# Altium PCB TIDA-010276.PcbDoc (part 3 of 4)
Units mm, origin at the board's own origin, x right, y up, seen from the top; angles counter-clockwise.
Board outline 146.48 x 90.27 mm, 4 copper layers (Top Layer, Signal Layer1, Signal Layer2, Bottom Layer), stack 1.631 mm thick; 271 components, 98 nets, 671 pads, 1828 vias.
Unrouted connection lines stored in the file: 2.
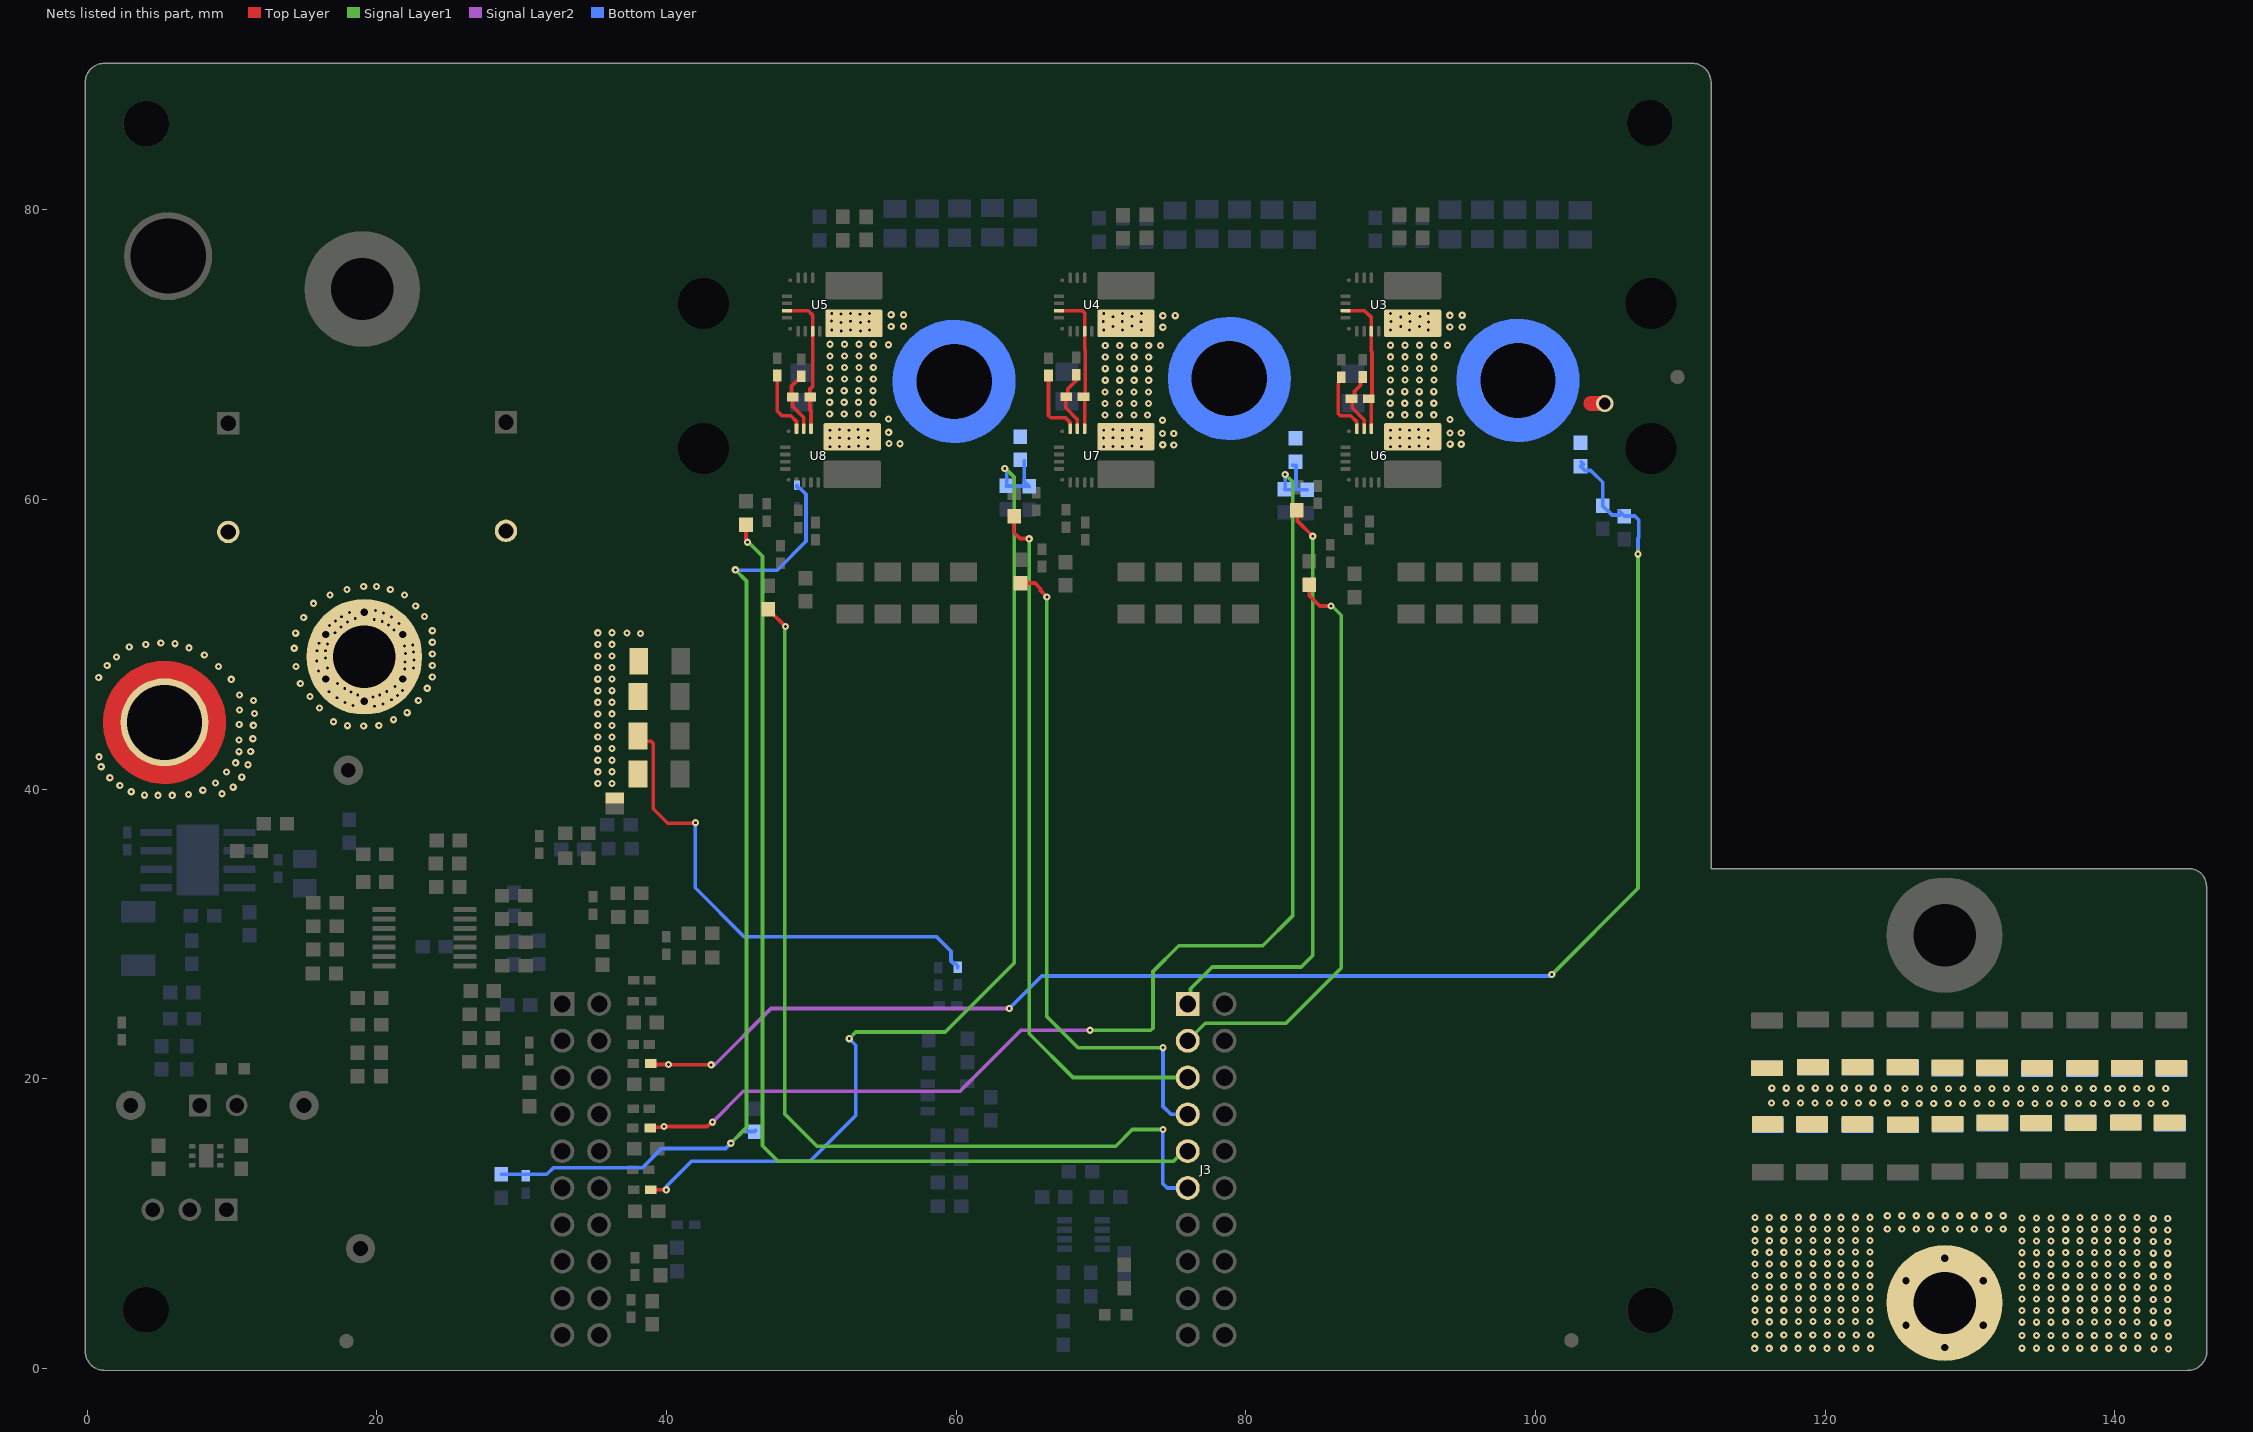
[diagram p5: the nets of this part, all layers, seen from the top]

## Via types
v1: diameter 0.5, hole 0.2, Top Layer to Bottom Layer, tented both sides, 1031 vias
v2: diameter 0.5, hole 0.2, Top Layer to Bottom Layer, 766 vias
v3: diameter 1, hole 0.5, Top Layer to Bottom Layer, 24 vias
v4: diameter 0.63, hole 0.33, Top Layer to Bottom Layer, tented both sides, 6 vias
v5: diameter 1.2, hole 0.8, Top Layer to Bottom Layer, 1 vias

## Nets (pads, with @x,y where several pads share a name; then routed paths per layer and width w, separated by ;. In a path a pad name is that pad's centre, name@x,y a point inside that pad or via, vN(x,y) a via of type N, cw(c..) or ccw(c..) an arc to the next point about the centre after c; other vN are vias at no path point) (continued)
PGND: C1.2 C2.2 C3.2 C4.2 C5.2 C6.2 C7.2 C8.2 C9.2 C10.2 C11.2 C12.2 C13.2 C14.2 C15.2 C16.2 C17.2 C18.2 C19.2 C20.2 C21.2 C22.2 C23.2 C24.2 C25.2 C26.2 C27.2 C28.2 C29.2 C30.2 C31.2 C32.2 C33.2 C34.2 C35.2 C36.2 C37.2 C38.2 C39.2 C40.1 C41.1 C42.1 MHA3.1 MHA4.1 MP3.1 NT1.1 R41.1 R42.1 R43.1 R44.1 R45.2 | length 34.7
  Top Layer w0.254: NT1.1@36.443,39.343 NT1.1@36.443,39.394 ; R41.1@37.844,48.83 R41.1@38.094,48.83 ; R43.1@37.965,43.307 38.945,43.307 39.093,43.158 39.093,38.645 40.094,37.644 41.971,37.644 v1(42.012,37.685)
  Bottom Layer w0.254: v1(42.012,37.685) 41.989,37.662 41.989,33.194 45.366,29.817 58.646,29.817 59.656,28.807 59.656,28.144 59.831,27.969 59.944,27.969 60.104,27.809 R45.2@60.104,27.696
  other v1: 142.708,1.355 143.708,1.355 115.137,1.398 116.137,1.398 117.137,1.398 118.137,1.398 119.137,1.398 120.137,1.398 121.137,1.398 122.137,1.398 123.137,1.398 133.59,1.408 134.59,1.408 135.59,1.408 136.59,1.408 137.59,1.408 138.59,1.408 139.59,1.408 140.59,1.408 141.59,1.408 142.708,2.237 143.708,2.237 133.59,2.29 134.59,2.29 135.59,2.29 136.59,2.29 137.59,2.29 138.59,2.29 139.59,2.29 140.59,2.29 141.59,2.29 115.152,2.311 116.152,2.311 117.152,2.311 118.152,2.311 119.152,2.311 120.152,2.311 121.152,2.311 122.152,2.311 123.152,2.311 142.659,3.169 143.659,3.169 133.59,3.205 134.59,3.205 135.59,3.205 115.152,3.225 116.152,3.225 117.152,3.225 136.608,3.222 137.608,3.222 138.608,3.222 139.541,3.222 140.541,3.222 141.541,3.222 118.17,3.243 119.17,3.243 120.17,3.243 121.103,3.243 122.103,3.243 123.103,3.243 142.659,3.969 143.659,3.969 133.59,4.005 134.59,4.005 135.59,4.005 115.152,4.025 116.152,4.025 117.152,4.025 118.17,4.043 119.17,4.043 120.17,4.043 121.103,4.043 122.103,4.043 123.103,4.043 136.608,4.022 137.608,4.022 138.608,4.022 139.541,4.022 140.541,4.022 141.541,4.022 142.659,4.769 143.659,4.769 133.59,4.805 134.59,4.805 135.59,4.805 115.152,4.825 116.152,4.825 117.152,4.825 136.608,4.822 137.608,4.822 138.608,4.822 139.541,4.822 140.541,4.822 141.541,4.822 118.17,4.843 119.17,4.843 120.17,4.843 121.103,4.843 122.103,4.843 123.103,4.843 142.659,5.569 143.659,5.569 133.59,5.605 134.59,5.605 135.59,5.605 115.152,5.625 116.152,5.625 117.152,5.625 118.17,5.643 119.17,5.643 120.17,5.643 121.103,5.643 122.103,5.643 123.103,5.643 136.608,5.622 137.608,5.622 138.608,5.622 139.541,5.622 140.541,5.622 141.541,5.622 142.659,6.369 143.659,6.369 133.59,6.405 134.59,6.405 135.59,6.405 115.152,6.425 116.152,6.425 117.152,6.425 136.608,6.422 137.608,6.422 138.608,6.422 139.541,6.422 140.541,6.422 141.541,6.422 118.17,6.443 119.17,6.443 120.17,6.443 121.103,6.443 122.103,6.443 123.103,6.443 142.659,7.169 143.659,7.169 133.59,7.205 134.59,7.205 135.59,7.205 115.152,7.225 116.152,7.225 117.152,7.225 118.17,7.243 119.17,7.243 120.17,7.243 121.103,7.243 122.103,7.243 123.103,7.243 136.608,7.222 137.608,7.222 138.608,7.222 139.541,7.222 140.541,7.222 141.541,7.222 142.659,7.969 143.659,7.969 133.59,8.005 134.59,8.005 135.59,8.005 115.152,8.025 116.152,8.025 117.152,8.025 136.608,8.022 137.608,8.022 138.608,8.022 139.541,8.022 140.541,8.022 141.541,8.022 118.17,8.043 119.17,8.043 120.17,8.043 121.103,8.043 122.103,8.043 123.103,8.043 142.659,8.769 143.659,8.769 133.59,8.805 134.59,8.805 135.59,8.805 115.152,8.825 116.152,8.825 117.152,8.825 118.17,8.843 119.17,8.843 120.17,8.843 121.103,8.843 122.103,8.843 123.103,8.843 136.608,8.822 137.608,8.822 138.608,8.822 139.541,8.822 140.541,8.822 141.541,8.822 142.659,9.569 143.659,9.569 133.59,9.605 134.59,9.605 135.59,9.605 115.152,9.625 116.152,9.625 117.152,9.625 136.608,9.622 137.608,9.622 138.608,9.622 139.541,9.622 140.541,9.622 141.541,9.622 118.17,9.643 119.17,9.643 120.17,9.643 121.103,9.643 122.103,9.643 123.103,9.643 124.297,9.643 125.297,9.643 126.297,9.643 127.297,9.643 128.297,9.643 129.297,9.643 130.297,9.643 131.297,9.643 132.297,9.643 142.659,10.369 143.659,10.369 133.59,10.405 134.59,10.405 135.59,10.405 115.152,10.425 116.152,10.425 117.152,10.425 118.17,10.443 119.17,10.443 120.17,10.443 121.103,10.443 122.103,10.443 123.103,10.443 136.608,10.422 137.608,10.422 138.608,10.422 139.541,10.422 140.541,10.422 141.541,10.422 124.297,10.554 125.297,10.554 126.297,10.554 127.297,10.554 128.297,10.554 129.297,10.554 130.297,10.554 131.297,10.554 132.297,10.554 125.495,18.307 126.495,18.307 127.495,18.307 128.495,18.307 129.495,18.307 130.495,18.307 131.495,18.307 132.495,18.307 133.495,18.307 134.495,18.307 135.495,18.307 136.495,18.307 137.495,18.307 138.495,18.307 139.495,18.307 140.495,18.307 141.495,18.307 142.495,18.307 143.495,18.307 116.298,18.329 117.298,18.329 118.298,18.329 119.298,18.329 120.298,18.329 121.298,18.329 122.298,18.329 123.298,18.329 124.298,18.329 116.325,19.359 117.325,19.359 118.325,19.359 119.325,19.359 120.325,19.359 121.325,19.359 122.325,19.359 123.325,19.359 124.325,19.359 125.522,19.337 126.522,19.337 127.522,19.337 128.522,19.337 129.522,19.337 130.522,19.337 131.522,19.337 132.522,19.337 133.522,19.337 134.522,19.337 135.521,19.337 136.521,19.337 137.521,19.337 138.521,19.337 139.521,19.337 140.521,19.337 141.521,19.337 142.521,19.337 143.521,19.337 4.898,39.577 5.886,39.577 3.969,39.592 7,39.632 9.315,39.684 3.052,39.826 7.996,39.931 10.091,40.142 2.264,40.26 8.873,40.421 1.575,40.792 10.685,40.831 9.633,41.181 0.978,41.548 11.119,41.692 10.263,41.822 0.819,42.234 10.485,42.591 11.299,42.598 10.499,43.404 11.447,43.487 19.098,44.36 17.989,44.386 20.145,44.398 11.482,44.412 10.507,44.464 17.018,44.661 21.167,44.802 11.561,45.227 22.104,45.287 10.533,45.467 16.051,45.603 19.838,45.73 18.362,45.778 20.437,45.895 17.82,45.997 11.497,46.122 22.875,46.129 21.034,46.175 17.259,46.314 19.756,46.379 15.392,46.403 21.422,46.463 10.533,46.496 18.69,46.507 20.212,46.51 18.225,46.704 16.708,46.73 20.691,46.746 21.772,46.814 17.794,46.964 23.487,46.971 21.253,47.09 14.727,47.303 17.299,47.312 9.961,47.589 0.803,47.708 23.841,47.745 15.986,48.165 21.933,48.299 16.594,48.368 22.53,48.357 9.083,48.469 14.426,48.465 1.389,48.538 23.841,48.545 21.959,48.783 15.861,48.84 22.578,48.934 16.478,49.053 2.043,49.128 8.099,49.269 21.991,49.357 23.841,49.345 22.539,49.463 15.89,49.564 16.478,49.564 14.31,49.73 7.038,49.76 2.918,49.813 21.92,49.889 22.488,49.957 4.051,49.998 16.612,50.026 6.066,50.048 5.094,50.093 16.015,50.075 23.841,50.145 14.403,50.775 17.111,50.803 23.841,50.945 21.19,50.995 17.525,51.188 16.746,51.303 20.814,51.342 21.544,51.436 17.996,51.544 20.381,51.572 17.15,51.601 19.833,51.717 18.516,51.794 14.958,51.858 21.016,51.88 17.563,51.909 23.301,51.926 20.468,52.169 18.121,52.198 19.91,52.342 22.692,52.645 15.632,52.836 16.778,53.407 21.911,53.407 17.955,53.788 20.942,53.788 19.098,54 19.99,54
  other v2: 35.266,40.398 36.238,40.403 35.266,41.198 36.238,41.203 35.266,41.998 36.238,42.003 35.266,42.798 36.238,42.803 35.266,43.598 36.238,43.603 35.266,44.398 36.238,44.403 35.266,45.198 36.238,45.203 35.266,45.998 36.238,46.003 35.266,46.798 36.238,46.803 35.266,47.598 36.238,47.603 35.266,48.398 36.238,48.403 35.266,49.198 36.238,49.203 35.266,49.998 36.238,50.003 38.215,50.757 35.266,50.798 36.238,50.803 37.278,50.791
  other v3: 128.254,1.46 125.591,2.998 130.917,2.998 125.591,6.072 130.917,6.072 128.254,7.61 19.143,46.069 16.48,47.607 21.806,47.607 16.48,50.681 21.806,50.681 19.143,52.219
Phase_U: MP2.1 R71.2 U3.6 U6.7 | length 1
  Top Layer w0.254: v5@104.796,66.628 v5(104.799,66.631)
  Top Layer w1.016: 103.83,66.628 v5@104.796,66.628
  other v1: 90,63.647 91.3,63.647 92.6,63.647 90,64.787 91.3,64.787 92.6,64.787 90,71.716 91.3,71.716 92.6,71.716 90,72.856 91.3,72.856 92.6,72.856
  other v2: 90.649,63.678 91.961,63.703 94.114,63.825 94.88,63.815 92.592,64.212 91.296,64.232 89.991,64.246 90.635,64.268 91.954,64.286 94.096,64.602 94.872,64.601 90.642,64.844 91.936,64.847 94.095,65.52 89.978,65.847 90.978,65.847 91.978,65.847 92.978,65.847 89.978,66.647 90.978,66.647 91.978,66.647 92.978,66.647 89.978,67.447 90.978,67.447 91.978,67.447 92.978,67.447 89.995,68.251 90.995,68.251 91.995,68.251 92.995,68.251 89.995,69.051 90.995,69.051 91.995,69.051 92.995,69.051 89.995,69.851 90.995,69.851 91.995,69.851 92.995,69.851 89.995,70.651 90.995,70.651 91.995,70.651 92.995,70.651 93.938,70.651 94.093,71.916 94.951,71.921 90.7,71.942 92.009,71.958 92.631,72.257 90.025,72.284 91.339,72.287 90.706,72.608 92.022,72.629 94.093,72.716 94.951,72.721
Phase_V: MP4.1 R72.2 U4.6 U7.7
  other v1: 70.2,63.647 71.5,63.647 72.8,63.647 70.2,64.787 71.5,64.787 72.8,64.787 70.2,71.716 71.5,71.716 72.8,71.716 70.2,72.856 71.5,72.856 72.8,72.856
  other v2: 70.846,63.674 72.158,63.7 74.272,63.783 75.038,63.773 72.789,64.208 70.188,64.242 71.493,64.229 70.833,64.264 72.151,64.282 74.254,64.56 75.029,64.559 70.839,64.84 72.134,64.844 74.253,65.478 70.281,65.83 71.281,65.83 72.281,65.83 73.216,65.836 70.281,66.63 71.281,66.63 72.281,66.63 73.281,66.63 70.281,67.43 71.281,67.43 72.281,67.43 73.281,67.43 70.299,68.234 71.299,68.234 72.299,68.234 73.299,68.234 70.299,69.034 71.299,69.034 72.299,69.034 73.299,69.034 70.299,69.834 71.299,69.834 72.299,69.834 73.299,69.834 70.299,70.634 71.299,70.634 72.299,70.634 73.299,70.634 74.122,70.627 74.277,71.892 70.838,71.958 72.148,71.974 72.769,72.273 70.164,72.3 71.477,72.302 70.844,72.624 72.161,72.644 74.277,72.692 75.135,72.697
Phase_W: MP5.1 R73.2 U5.6 U8.7
  other v1: 51.309,63.647 52.609,63.647 53.909,63.647 51.309,64.787 52.609,64.787 53.909,64.787 51.42,71.716 52.72,71.716 54.02,71.716 51.42,72.856 52.72,72.856 54.02,72.856
  other v2: 51.955,63.673 53.268,63.699 55.363,63.862 56.129,63.852 53.899,64.207 51.297,64.242 52.603,64.228 51.942,64.264 53.261,64.282 55.345,64.639 51.948,64.84 53.243,64.843 55.344,65.557 51.273,65.914 52.273,65.914 53.273,65.914 54.273,65.914 51.273,66.714 52.273,66.714 53.273,66.714 54.273,66.714 51.273,67.514 52.273,67.514 53.273,67.514 54.273,67.514 51.29,68.319 52.29,68.319 53.29,68.319 54.29,68.319 51.29,69.119 52.29,69.119 53.29,69.119 54.29,69.119 51.29,69.919 52.29,69.919 53.29,69.919 54.29,69.919 55.336,70.685 51.29,70.719 52.29,70.719 53.29,70.719 54.29,70.719 52.071,71.637 53.4,71.647 55.52,71.956 56.378,71.961 52.058,72.227 53.393,72.229 53.998,72.292 52.702,72.312 51.396,72.326 55.52,72.756 56.378,72.761 52.065,72.803 53.375,72.791
Temp: C123.1 R58.1 R87.2 RT1.2 | length 69.1
  Signal Layer1 w0.254: v1(44.45,15.559) 45.534,16.643 45.534,54.374 v1(44.763,55.145)
  Bottom Layer w0.254: C123.1@28.595,13.413 31.747,13.413 32.189,13.856 38.328,13.856 39.662,15.19 44.082,15.19 v1(44.45,15.559) 45.265,16.374 46.095,16.374 R58.1@46.159,16.438 ; v1(44.763,55.145) 44.791,55.117 47.648,55.117 49.644,57.112 49.644,60.365 49.227,60.782 49.092,60.782 49.019,60.855 RT1.2@49.019,60.99
U_H: J3.1 R16.2 | length 42.2
  Top Layer w0.254: J3.1@75.819,25.2 J3.1@76.19,25.572 ; R16.2@83.527,59.245 83.578,59.193 83.578,58.512 v1(84.625,57.465)
  Signal Layer1 w0.254: J3.1@75.997,25.171 76.19,25.365 76.19,26.229 77.69,27.728 83.838,27.728 84.625,28.515 v1(84.625,57.465)
U_HO: R10.1 U6.10 | length 4.6
  Top Layer w0.254: R10.1@86.593,68.444 86.42,68.271 86.42,68.054 86.388,68.022 86.388,65.941 86.537,65.792 87.245,65.792 87.675,65.362 U6.10@87.675,64.887
U_L: J3.3 R19.2 | length 40.4
  Top Layer w0.254: R19.2@84.384,54.129 84.384,53.379 85.118,52.645 v1(85.885,52.645)
  Signal Layer1 w0.254: J3.3@75.997,22.631 77.212,23.846 82.782,23.846 86.6,27.665 86.6,52.004 v1@86.01,52.594
U_SW: C81.2 U3.4 U3.14 U6.8 | length 9.9
  Top Layer w0.254: U3.14@86.9,73.041 88.205,73.041 88.675,72.571 U3.4@88.675,71.616 88.675,70.242 88.717,70.2 88.717,67.125 88.544,66.952 C81.2@88.501,66.952 88.675,66.779 U6.8@88.675,64.887
U_VCC: C81.1 R7.1 U6.9 | length 4
  Top Layer w0.254: R7.1@88.087,68.463 87.929,68.305 87.929,67.89 87.511,67.472 87.511,67.112 87.351,66.952 87.351,66.333 88.173,65.511 U6.9@88.173,65.11
U_Voltage: C117.1 R71.1 R75.2 R85.1 | length 105.8
  Top Layer w0.254: R85.1@38.915,21.061 38.987,20.989 v1(40.137,20.989) 40.146,20.98 43.082,20.98 v1(43.091,20.972)
  Signal Layer2 w0.254: v1(43.091,20.972) 43.336,20.972 47.227,24.863 v1(63.67,24.863)
  Signal Layer1 w0.254: v1@101.173,27.249 107.081,33.157 107.081,56.488
  Bottom Layer w0.254: v1(63.67,24.863) 65.914,27.107 v1@101.173,27.107 ; R71.1@103.121,62.312 103.424,62.009 103.824,62.009 104.643,61.19 104.643,59.554 104.991,59.206 105.016,59.206 105.287,58.935 R75.2@105.846,58.935 ; R71.1@103.165,62.6 R71.1@103.32,62.445 ; R75.2@105.781,59.233 106.129,58.885 R75.2@106.129,58.86 106.859,58.86 107.132,58.587 107.132,57.385 107.081,57.334 v1(107.081,56.231)
  other v1: 101.128,27.204
V_H: J3.5 R17.2 | length 48.8
  Top Layer w0.254: R17.2@64.014,58.862 63.985,58.833 63.985,57.746 64.416,57.315 65.02,57.315 v1(65.047,57.288)
  Signal Layer1 w0.254: v1(65.047,57.288) 65.047,23.117 68.073,20.091 J3.5@75.997,20.091
V_HO: R11.1 U7.10 | length 4.7
  Top Layer w0.254: R11.1@66.384,68.564 66.384,65.793 66.533,65.644 67.551,65.644 67.873,65.322 U7.10@67.873,65.11
V_L: J3.7 R20.2 | length 47
  Top Layer w0.254: R20.2@64.458,54.236 65.443,54.236 65.833,53.846 65.833,53.724 66.269,53.288 v1(66.269,53.268)
  Signal Layer1 w0.254: v1(66.269,53.268) 66.269,24.314 68.427,22.156 v1(74.289,22.156)
  Bottom Layer w0.254: v1(74.289,22.156) 74.289,18.1 74.837,17.551 J3.7@75.997,17.551 ; J3.7@76.043,17.912 76.357,17.912 J3.7@76.718,17.551
V_SW: C82.2 U4.4 U4.14 U7.8 | length 9.9
  Top Layer w0.254: U4.14@67.1,73.041 68.726,73.041 68.875,72.892 U4.4@68.875,71.616 68.875,70.4 68.931,70.344 68.931,67.278 68.914,67.262 68.875,67.262 U7.8@68.875,64.887
V_VCC: C82.1 R8.1 U7.9 | length 4.4
  Top Layer w0.254: R8.1@68.252,68.559 R8.1@68.3,68.607 ; R8.1@68.365,68.559 68.365,68.292 67.711,67.637 67.711,67.251 67.565,67.105 67.565,66.344 68.375,65.535 U7.9@68.375,64.887
V_Voltage: C118.1 R72.1 R76.2 R86.1 | length 87.8
  Top Layer w0.254: R86.1@38.884,16.608 38.942,16.666 39.78,16.666 v1(39.827,16.713) 42.811,16.713 43.112,17.014 v1(43.178,17.014)
  Signal Layer2 w0.254: v1(43.178,17.014) 45.314,19.149 60.276,19.149 64.482,23.355 v1(69.242,23.355)
  Signal Layer1 w0.254: v1(69.242,23.355) 73.45,23.355 73.598,23.504 73.598,27.415 75.368,29.185 81.167,29.185 83.236,31.253 83.236,61.223 v1(82.722,61.737)
  Bottom Layer w0.254: v1(82.722,61.737) 82.722,60.746 C118.1@82.684,60.707 82.722,60.669 83.464,60.669 ; R72.1@83.255,62.389 R72.1@83.284,62.36 ; R72.1@83.464,62.378 83.464,60.669 ; R76.2@84.252,60.669 83.464,60.669
W_H: J3.9 R18.2 | length 73.5
  Top Layer w0.254: R18.2@45.492,58.267 45.492,57.224 45.598,57.118 v1(45.598,57.051)
  Signal Layer1 w0.254: v1(45.598,57.051) 45.665,57.051 45.788,56.928 45.793,56.928 46.633,56.088 46.633,15.391 47.72,14.305 74.998,14.305 75.705,15.011 J3.9@75.997,15.011
W_HO: R12.1 U8.10 | length 4.6
  Top Layer w0.254: R12.1@47.657,68.564 47.658,66.115 47.988,65.784 48.588,65.784 48.984,65.388 U8.10@48.984,64.887
W_L: J3.11 R21.2 | length 68.4
  Top Layer w0.254: R21.2@46.991,52.364 47.079,52.364 v1(48.216,51.226)
  Signal Layer1 w0.254: v1(48.216,51.226) 48.178,51.188 48.178,17.582 50.401,15.358 71.017,15.358 72.165,16.506 v1(74.279,16.506)
  Bottom Layer w0.254: v1(74.279,16.506) 74.279,12.766 74.574,12.471 J3.11@75.997,12.471
W_SW: C83.2 U5.4 U5.14 U8.8 | length 9.9
  Top Layer w0.254: U5.14@48.32,73.041 49.787,73.041 50.095,72.733 50.095,67.809 49.922,67.636 49.912,67.636 49.912,66.186 49.984,66.115 U8.8@49.984,64.887
W_VCC: C83.1 R9.1 U8.9 | length 4.3
  Top Layer w0.254: 48.71,66.415 C83.1@48.71,67.074 ; C83.1@48.719,67.074 48.635,67.158 48.635,67.831 49.03,68.225 49.13,68.225 49.303,68.398 R9.1@49.303,68.498 ; 48.759,66.395 49.484,65.669 U8.9@49.484,64.887
W_Voltage: C119.1 R73.1 R77.2 R88.1 | length 74.6
  Top Layer w0.254: R88.1@38.934,12.355 38.949,12.339 v1(39.99,12.339)
  Signal Layer1 w0.254: v1(52.622,22.78) 53.079,23.236 59.254,23.236 64.009,27.992 64.009,61.556 63.428,62.137 v1(63.362,62.137)
  Bottom Layer w0.254: v1(39.99,12.339) 40.038,12.388 40.038,12.628 41.715,14.305 49.904,14.305 53.079,17.48 53.079,22.324 v1(52.622,22.78) ; v1(63.362,62.137) 63.362,62.07 63.493,61.939 63.493,60.959 C119.1@63.473,60.938 R77.2@65.025,60.938 ; R73.1@64.712,62.671 64.712,61.424 64.713,61.423 64.713,61.25 R77.2@65.025,60.938 ; R77.2@65.061,60.902 R77.2@65.025,60.938
pads on no net: FID1.1 FID2.1 FID3.1 J3.4 J3.6 J3.8 J3.10 J3.12 J3.14 J3.15 J3.16 J3.17 J3.18 J3.19 J4.5 J4.7 J4.9 J4.13 J4.15 J4.17 J4.19 J4.20 MP1. MP2. MP3. MP4. MP5. MP6. MP7. MP8. MP9. U1.5 U1.7@8.238,14.24 U1.7@8.238,15.14 U2.6 U3.1 U3.5 U3.8 U3.9 U3.10 U3.11 U3.12 U3.13 U3.15 U4.1 U4.5 U4.8 U4.9 U4.10 U4.11 U4.12 U4.13 U4.15 U5.1 U5.5 U5.8 U5.9 U5.10 U5.11 U5.12 U5.13 U5.15 U6.1 U6.5 U6.11 U6.12 U6.13 U6.15 U7.1 U7.5 U7.11 U7.12 U7.13 U7.15 U8.1 U8.5 U8.11 U8.12 U8.13 U8.15 U11.5 U11.6 U11.7

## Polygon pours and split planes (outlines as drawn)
GND on Top Layer "TOP_LAYER_GND_P200" (solid, remove dead copper, pour order 200): 0.088,38.608 112.079,38.608 112.079,-0.061 0.088,-0.061
BAT+ on Top Layer "TOP_LAYER_BAT+_P246" (solid, pour order 246): 113.97,34.392 113.97,-0.122 113.977,-0.115 146.089,-0.115 146.089,15.056 146.089,34.355
PGND on Top Layer "TOP_LAYER_PGND_P221" (solid, pour order 221): 114.054,22.426 146.173,22.426 146.173,15.948 146.173,15.347 114.054,15.347
BAT+ on Top Layer "Top Layer-BAT+" (solid, remove dead copper, pour order 206): 47.265,74.969 51.006,74.969 51.006,73.838 112.041,73.838 112.041,90.037 0.773,90.124 -0.051,89.301 -0.051,78.375 0.001,78.375 0.001,63.89 45.315,63.89 45.315,74.969
GaN_U_AGND on Top Layer "TOP_LAYER_GAN_U_AGND_P204" (solid, pour order 204): 89.367,80.488 89.367,79.049 89.426,78.987 93.376,78.987 93.442,79.053 93.434,80.434 93.334,80.534 89.404,80.534
GaN_V_AGND on Top Layer "TOP_LAYER_GAN_V_AGND_P203" (solid, pour order 203): 70.392,80.552 70.392,79.113 70.451,79.051 74.401,79.051 74.467,79.116 74.46,80.497 74.359,80.597 70.429,80.597
GaN_W_AGND on Top Layer "TOP_LAYER_GAN_W_AGND_P205" (solid, pour order 205): 51.043,80.422 51.043,78.983 51.102,78.921 55.052,78.921 55.118,78.987 55.111,80.367 55.01,80.468 51.08,80.468
PGND on Top Layer "Top Layer-PGND" (solid, remove dead copper, pour order 207): 46.047,62.2 46.169,62.322 46.168,62.324 46.047,62.324 46.047,62.332 29.824,62.332 -0.05,62.332 -0.05,39.395 0.039,39.306 38.763,39.306 38.763,50.435 45.151,54.722 45.151,57.681 45.534,57.686 46.037,58.166
GaN_U_AGND on Top Layer "TOP_LAYER_GAN_U_AGND_P219" (solid, pour order 219): 89.587,62.688 89.605,62.671 89.605,55.183 90.361,54.427 103.639,54.427 103.639,62.731
GaN_V_AGND on Top Layer "TOP_LAYER_GAN_V_AGND_P217" (solid, pour order 217): 69.746,62.678 69.764,62.66 69.764,54.581 69.928,54.416 81.125,54.416 81.125,62.712
NetR25_1 on Top Layer "TOP_LAYER_NETR25_1_P215" (solid, pour order 215): 40.037,50.29 40.037,39.313 111.48,39.313 111.48,52.906 108.514,52.906 43.854,52.796
GaN_W_AGND on Top Layer "TOP_LAYER_GAN_W_AGND_P213" (solid, pour order 213): 50.834,62.624 50.852,62.606 50.852,55.109 51.598,54.363 62.104,54.363 62.213,54.472 62.213,62.658
Phase_U on Top Layer "TOP_LAYER_PHASE_U_P211" (solid, pour order 211): 89.533,72.021 89.533,73.089 104.117,73.089 104.117,63.778 103.761,63.422 89.473,63.422
Phase_V on Top Layer "TOP_LAYER_PHASE_V_P209" (solid, pour order 209): 69.87,73.115 84.061,73.115 84.061,63.706 83.773,63.418 69.802,63.418
Phase_W on Top Layer "TOP_LAYER_PHASE_W_P208" (solid, pour order 208): 50.971,72.059 50.971,73.11 64.756,73.11 64.756,63.714 64.46,63.418 50.834,63.418
GND on Bottom Layer "BOTTOM_LAYER_GND_P201" (solid, remove dead copper, pour order 201): -0.126,38.593 112.127,38.593 112.127,0 -0.126,0
PGND on Bottom Layer "BOTTOM_LAYER_PGND_P245" (solid, pour order 245): 113.97,34.392 114.046,34.468 146.305,34.468 146.305,0.101 146.089,-0.115 145.986,-0.011 113.916,-0.011 113.916,-0.068 113.97,-0.122
BAT+ on Bottom Layer "BOTTOM_LAYER_BAT+_P243" (solid, pour order 243): 114.956,14.213 144.946,14.213 144.946,12.065 114.956,12.065
BAT+ on Bottom Layer "Bottom Layer-BAT+" (solid, remove dead copper, pour order 220): 0.001,77.775 0.001,64.246 0.356,63.89 46.031,63.89 46.031,73.845 112.127,73.828 112.127,90 8.42,90 8.42,89.353 6.971,89.353 6.971,83.301 0.001,83.301 -0.051,77.775
PGND on Bottom Layer "BOTTOM_LAYER_PGND_P228" (solid, pour order 228): 0.52,62.332 38.763,62.332 45.151,59.7 45.151,54.722 43.783,53.788 38.763,50.435 38.763,39.306 0.618,39.306 0.52,39.403
GaN_U_AGND on Bottom Layer "BOTTOM_LAYER_GAN_U_AGND_P212" (solid, pour order 212): 89.622,62.629 89.689,62.697 103.639,62.757 103.639,51.158 89.954,51.158 89.622,51.49
GaN_U_AGND on Bottom Layer "BOTTOM_LAYER_GAN_U_AGND_P218" (solid, pour order 218): 88.485,80.847 88.261,80.704 88.261,79.041 88.377,78.925 103.931,78.925 104.032,79.026 104.036,80.747 103.946,80.847
GaN_V_AGND on Bottom Layer "BOTTOM_LAYER_GAN_V_AGND_P216" (solid, pour order 216): 69.305,80.795 69.16,80.625 69.16,79.021 69.309,78.872 85.075,78.872 85.176,78.974 85.181,80.694 85.09,80.795
GaN_W_AGND on Bottom Layer "BOTTOM_LAYER_GAN_W_AGND_P214" (solid, pour order 214): 49.963,80.926 49.818,80.756 49.818,79.152 49.967,79.004 65.732,79.004 65.834,79.105 65.838,80.825 65.748,80.926
BAT+ on Bottom Layer "BOTTOM_LAYER_BAT+_P244" (solid, pour order 244): 114.096,34.392 146.336,34.392 146.336,23.169 114.096,23.169
NetR25_1 on Bottom Layer "BOTTOM_LAYER_NETR25_1_P227" (solid, pour order 227): 40.037,50.29 42.247,51.759 43.812,52.783 111.48,52.919 111.48,39.313 40.037,39.313
Phase_U on Bottom Layer "BOTTOM_LAYER_PHASE_U_P226" (solid, pour order 226): 89.54,73.115 104.096,73.115 104.096,63.757 103.761,63.422 89.473,63.422
Phase_V on Bottom Layer "BOTTOM_LAYER_PHASE_V_P224" (solid, pour order 224): 69.749,73.109 69.837,63.562 69.725,63.45 69.758,63.418 83.443,63.418 84.057,64.032 84.057,64.698 84.057,73.109
Phase_W on Bottom Layer "BOTTOM_LAYER_PHASE_W_P222" (solid, pour order 222): 51.002,73.084 64.818,73.084 64.818,63.776 64.46,63.418 50.834,63.418
GaN_V_AGND on Bottom Layer "BOTTOM_LAYER_GAN_V_AGND_P210" (solid, pour order 210): 69.758,62.684 69.71,51.657 70.158,51.208 81.125,51.208 81.125,62.725
GaN_W_AGND on Bottom Layer "BOTTOM_LAYER_GAN_W_AGND_P202" (solid, remove dead copper, pour order 202): 50.834,62.624 50.856,62.602 50.856,51.766 51.415,51.208 61.865,51.208 62.213,51.556 62.213,62.658
GND on Signal Layer2 "Signal Layer1-GND" (solid, remove dead copper, pour order 223): 0.001,-0.174 112.127,-0.174 112.127,38.069 112.825,38.071 112,38.896 -0.05,38.896 -0.05,38.634 0.001,38.583
BAT+ on Signal Layer2 "SIGNAL_LAYER2_BAT+_P242" (solid, pour order 242): 114.096,34.507 114.096,-0.007 114.103,0 146.215,0 146.215,15.171 146.215,34.47
PGND on Signal Layer2 "Top Layer-PGND" (solid, remove dead copper, pour order 234): 46.047,62.2 46.169,62.322 46.168,62.324 46.047,62.324 46.047,62.332 29.824,62.332 -0.05,62.332 -0.05,39.395 0.039,39.306 38.763,39.306 38.763,50.435 45.151,54.722 45.151,57.681 45.534,57.686 46.037,58.166
BAT+ on Signal Layer2 "SIGNAL_LAYER2_BAT+_P199" (solid, remove dead copper, pour order 199): 0.001,90 0.001,63.89 46.031,63.89 46.031,73.778 112.126,73.778 112.126,90 85.782,90 0.001,90
GaN_U_AGND on Signal Layer2 "SIGNAL_LAYER2_GAN_U_AGND_P240" (solid, pour order 240): 89.6,62.592 89.689,62.681 89.689,62.697 100.851,62.697 100.876,62.723 100.966,62.633 100.966,54.427 89.745,54.427 89.573,54.599
GaN_V_AGND on Signal Layer2 "SIGNAL_LAYER2_GAN_V_AGND_P239" (solid, pour order 239): 69.755,61.867 69.755,61.941 69.755,62.669 80.938,62.712 81.036,62.712 81.755,62.712 81.755,54.416 81.108,54.416 69.928,54.416 69.765,54.58
GaN_W_AGND on Signal Layer2 "SIGNAL_LAYER2_GAN_W_AGND_P238" (solid, pour order 238): 50.851,62.59 50.932,62.671 50.932,62.684 62.188,62.684 62.213,62.658 62.213,54.472 62.104,54.363 51.024,54.363 50.851,54.536
NetR25_1 on Signal Layer2 "SIGNAL_LAYER2_NETR25_1_P233" (solid, pour order 233): 40.037,50.29 40.037,39.313 111.48,39.313 111.48,52.906 108.514,52.906 43.854,52.796
Phase_U on Signal Layer2 "SIGNAL_LAYER2_PHASE_U_P232" (solid, pour order 232): 89.536,73.089 104.117,73.089 104.117,63.778 103.774,63.435 89.469,63.435
Phase_V on Signal Layer2 "SIGNAL_LAYER2_PHASE_V_P231" (solid, pour order 231): 69.812,73.115 69.899,63.601 69.788,63.49 69.821,63.457 83.813,63.457 84.12,63.764 84.12,73.115
Phase_W on Signal Layer2 "SIGNAL_LAYER2_PHASE_W_P230" (solid, pour order 230): 51.002,73.084 64.756,73.084 64.756,63.714 64.46,63.418 50.834,63.418
GND on Signal Layer1 "Signal Layer1-GND 1" (solid, remove dead copper, pour order 237): -0.047,37.045 -0.046,0.12 0.135,-0.061 112.079,-0.061 112.079,38.499 112.06,38.499 112.06,62.405 -0.066,62.405 -0.066,37.045
PGND on Signal Layer1 "SIGNAL_LAYER1_PGND_P241" (solid, remove dead copper, pour order 241): 114.096,34.507 114.096,-0.007 114.103,0 146.215,0 146.215,15.171 146.215,34.47
BAT+ on Signal Layer1 "SIGNAL_LAYER1_BAT+_P225" (solid, remove dead copper, pour order 225): -0.041,90.08 -0.041,63.971 45.327,63.971 45.327,82.271 112.085,82.271 112.085,90.08 85.741,90.08 -0.04,90.08
GaN_U_AGND on Signal Layer1 "SIGNAL_LAYER1_GAN_U_AGND_P229" (solid, remove dead copper, pour order 229): 86.144,80.636 86.386,80.878 103.609,80.878 103.609,56.94 86.144,56.94
GaN_W_AGND on Signal Layer1 "SIGNAL_LAYER1_GAN_W_AGND_P235" (solid, remove dead copper, pour order 235): 47.415,80.539 47.657,80.781 64.88,80.781 64.88,63.46 62.203,61.612 62.203,56.841 47.415,56.843
GaN_V_AGND on Signal Layer1 "SIGNAL_LAYER1_GAN_V_AGND_P236" (solid, remove dead copper, pour order 236): 66.345,80.645 66.586,80.886 83.809,80.886 83.809,63.663 81.124,61.652 81.124,56.942 66.345,56.948
BAT+ on Bottom Solder "NONET_L-01_P-001" (solid): 89.592,75.75 89.511,75.656 89.511,73.902 89.558,73.849 93.373,73.871 93.462,73.96 93.462,75.679 93.391,75.75
no net on Bottom Solder "NONET_L-01_P-001" (solid): 89.613,65.28 89.532,65.187 89.532,63.433 89.579,63.38 93.394,63.402 93.483,63.491 93.483,65.209 93.412,65.28
no net on Bottom Solder "NONET_L-01_P-001" (solid): 50.931,65.234 50.85,65.141 50.85,63.387 50.897,63.333 54.712,63.356 54.801,63.445 54.801,65.163 54.73,65.234
W_SW on Bottom Solder "NONET_L-01_P-001" (solid): 51.042,73.092 50.962,72.998 50.962,71.244 51.008,71.191 54.823,71.213 54.912,71.302 54.912,73.02 54.841,73.092
BAT+ on Bottom Solder "NONET_L-01_P-001" (solid): 51.084,75.748 51.003,75.655 51.003,73.901 51.05,73.848 54.865,73.87 54.954,73.959 54.954,75.677 54.883,75.748
BAT+ on Bottom Solder "NONET_L-01_P-001" (solid): 51.084,75.748 51.003,75.655 51.003,73.901 51.05,73.848 54.865,73.87 54.954,73.959 54.954,75.677 54.883,75.748
V_SW on Bottom Solder "NONET_L-01_P-001" (solid): 69.839,73.123 69.759,73.029 69.759,71.275 69.805,71.222 73.62,71.244 73.709,71.333 73.709,73.052 73.638,73.123
BAT+ on Bottom Solder "NONET_L-01_P-001" (solid): 69.822,75.668 69.742,75.574 69.742,73.82 69.788,73.767 73.603,73.789 73.692,73.878 73.692,75.597 73.621,75.668
U_SW on Bottom Solder "NONET_L-01_P-001" (solid): 89.623,73.107 89.542,73.013 89.542,71.259 89.589,71.206 93.403,71.228 93.493,71.317 93.493,73.036 93.421,73.107
GaN_V_AGND on Bottom Solder "NONET_L-01_P-001" (solid): 69.865,62.673 69.785,62.579 69.785,60.825 69.831,60.772 73.646,60.794 73.735,60.883 73.735,62.602 73.664,62.673
V_SW on Bottom Solder "NONET_L-01_P-001" (solid): 69.865,65.307 69.785,65.214 69.785,63.46 69.831,63.407 73.646,63.429 73.735,63.518 73.735,65.236 73.664,65.307
GaN_U_AGND on Bottom Solder "NONET_L-01_P-001" (solid): 89.62,62.685 89.54,62.591 89.54,60.837 89.586,60.784 93.401,60.806 93.49,60.895 93.49,62.614 93.419,62.685
GaN_W_AGND on Bottom Solder "NONET_L-01_P-001" (solid): 50.932,62.684 50.851,62.59 50.851,60.836 50.898,60.783 54.713,60.805 54.802,60.894 54.802,62.613 54.731,62.684

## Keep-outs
Keep-Out Layer:
  circle w0.254: c107.987,63.525 r3.5
  circle w0.254: c107.987,73.536 r3.5
  circle w0.254: c42.562,63.525 r3.5
  circle w0.254: c42.562,73.536 r3.5
  circle w0.254: c107.886,86.001 r4
  circle w0.254: c4.072,4.07 r4
  circle w0.254: c107.918,4.026 r4
  circle w0.254: c4.082,85.94 r4
  text ".Layer_Name" at -51.844,-91.306 h1.52

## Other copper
Top Layer:
  text ".Layer_Name" at -51.844,-91.306 h1.52
Bottom Layer:
  text ".Layer_Name" at -51.844,-91.306 h1.52

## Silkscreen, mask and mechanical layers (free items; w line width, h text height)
Top Overlay:
  text "BAT+" at 10.789,76.067 h2.03
  text "W" at 63.231,72.591 h2.03
  text "U" at 102.425,72.539 h2.03
  text "V" at 83.333,72.427 h2.03
  text "GND" at 10.716,43.335 h2.03
  text "BAT+" at 19.726,41.827 h0.76
  text "BAT+" at 133.47,29.417 h2.03
  text "3.3V" at 14.403,19.854 h0.76
  text "5V" at 2.614,19.803 h0.76
  text "GND" at 18.206,9.962 h0.76
  text "GND" at 133.26,3.64 h2.03
  text "TIDA-010276" at 85.877,2.642 h2.75
  text "Ver.B" at 97.078,0.759 h1.5
  text ".Layer_Name" at -51.844,-91.306 h1.52
Bottom Overlay:
  text "W" at 63.224,72.56 h2.03
  text "U" at 102.44,72.553 h2.03
  text "V" at 83.31,72.454 h2.03
  text ".Layer_Name" at -51.844,-91.306 h1.52
Top Paste:
  text ".Layer_Name" at -51.844,-91.306 h1.52
Bottom Paste:
  text ".Layer_Name" at -51.844,-91.306 h1.52
Top Solder:
  text ".Layer_Name" at -51.844,-91.306 h1.52
  text ".Layer_Name" at -51.844,-91.306 h1.52
Bottom Solder:
  text ".Layer_Name" at -51.844,-91.306 h1.52
Drill Guide:
  text ".Layer_Name" at -51.844,-91.306 h1.52
M1 Board Outline:
  lines w0.2: 112.291,32.59 112.291,1.631 ccw(c113.191,1.631) 114.091,1.631 ; 112.296,32.543 cw(c113.196,32.543) 114.096,32.543 114.096,1.555
  lines w0.254: 0,1.199 0,88.804 ; 0,88.799 cw(c1.204,88.793) 1.218,89.997 ; 0.001,88.798 0.001,1.217 ccw(c1.205,1.203) 1.199,0 ; 1.194,-0.012 145.011,-0.011 ; 1.199,0 108.783,0 ; 1.218,90 110.802,90 ; 110.802,89.999 cw(c110.797,88.795) 112,88.782 112,34.392 145.123,34.392 cw(c145.119,33.301) 146.209,33.288 146.228,1.194 cw(c145.024,1.199) 145.011,-0.004
  text ".Layer_Name" at -51.844,-91.306 h1.52
M2 Board Dimensions:
  circle w0.1: c107.975,63.551 r1.753
  circle w0.1: c107.95,73.558 r1.753
  circle w0.1: c42.596,63.5 r1.753
  circle w0.1: c42.596,73.508 r1.753
  rectangle: -63.325,-79.66 -53.8,-76.485
  rectangle: -66.5,-76.485 -63.325,-73.31
  lines w0.051: 39.262,77.052 111.276,77.052 111.276,60.045 39.276,60.045 ; 39.265,60.043 39.265,77.043 ; 39.264,51.48 111.299,51.48 111.299,81.445 111.286,81.459 39.264,81.459 39.264,51.48
  lines w0.178: -66.5,-76.485 -41.1,-76.485 ; -63.325,-79.66 -63.325,-73.31 ; -60.15,-79.66 -60.15,-73.31 ; -53.8,-79.66 -53.8,-73.31 ; -47.45,-79.66 -47.45,-73.31 ; -66.5,-79.66 -66.5,-73.31 -41.1,-73.31 -41.1,-79.66 -66.5,-79.66
  text "M3" at 47.244,72.212 h1.52
  text "M3" at 100.805,70.501 h1.52
  text "M3" at 101.054,65.097 h1.52
  text "M3" at 46.548,62.602 h1.52
  text ".Layer_Name" at -51.844,-91.306 h1.52
M3 3D STEP Top:
  text ".Layer_Name" at -51.844,-91.306 h1.52
M4 3D STEP Bottom:
  text ".Layer_Name" at -51.844,-91.306 h1.52
M5 Assembly Top:
  lines w0.254: -73.917,-93.126 93.723,-93.126 ; -73.917,-87.962 93.774,-87.962 ; -73.917,-82.797 -73.917,-98.291 27.81,-98.291 93.774,-98.291 93.774,-82.797 -73.904,-82.797 -73.904,-98.291 -33.886,-98.291 ; -11.306,-98.291 -11.306,-82.797 ; 20.876,-87.962 20.876,-82.797 ; 42.212,-87.962 42.212,-82.797 ; 58.011,-98.456 58.011,-93.304
  text "COMPONENTS MARKED 'DNP' SHOULD NOT BE POPULATED." at -37.201,-77.59 h1.52
  text "ASSEMBLY VARIANT:" at -37.214,-80.524 h1.52
  text ".VariantName" at -10.899,-80.524 h1.52
  text "PCB VIEWED FROM TOP SIDE" at -72.304,-86.154 h1.52
  text "BOARD #:" at -9.401,-86.154 h1.52
  text ".PRJ_Number" at 4.455,-86.154 h1.52
  text "REV:" at 25.905,-86.154 h1.52
  text ".PCB_Rev" at 33.309,-86.154 h1.52
  text "SVN REV:" at 47.19,-86.154 h1.52
  text ".VersionControl_RevNumber" at 60.043,-86.154 h1.52
  text "PLOT NAME =" at -72.304,-96.534 h1.52
  text ".plot_File_Name" at -51.844,-96.534 h1.52
  text "GENERATED    :" at -9.35,-96.534 h1.52
  text ".Print_Date" at 12.735,-96.534 h1.52
  text ".Print_Time" at 31.252,-96.534 h1.52
  text "TEXAS INSTRUMENTS" at 63.37,-96.534 h1.52
M6 Assembly Bottom:
  lines w0.254: -73.929,-87.974 93.761,-87.974 ; -73.879,-93.139 93.761,-93.139 ; -38.166,-98.469 -38.166,-93.317 ; -22.367,-87.974 -22.367,-82.81 ; -1.031,-87.974 -1.031,-82.81 ; 31.15,-98.304 31.15,-82.81 ; 53.731,-98.304 93.749,-98.304 93.749,-82.81 -73.929,-82.81 -73.929,-98.304 -7.966,-98.304 93.761,-98.304 93.761,-82.81
  text "COMPONENTS MARKED 'DNP' SHOULD NOT BE POPULATED." at 88.491,-77.577 h1.52
  text ".VariantName" at 61.973,-80.524 h1.52
  text "ASSEMBLY VARIANT:" at 88.364,-80.524 h1.52
  text ".VersionControl_RevNumber" at -40.198,-86.167 h1.52
  text "SVN REV:" at -27.346,-86.167 h1.52
  text ".PCB_Rev" at -13.465,-86.167 h1.52
  text "REV:" at -6.061,-86.167 h1.52
  text ".PRJ_Number" at 15.39,-86.167 h1.52
  text "BOARD #:" at 29.245,-86.167 h1.52
  text "PCB VIEWED FROM BOTTOM SIDE" at 92.148,-86.167 h1.52
  text "TEXAS INSTRUMENTS" at -43.526,-96.547 h1.52
  text ".Print_Time" at -11.407,-96.547 h1.52
  text ".Print_Date" at 7.109,-96.547 h1.52
  text "GENERATED    :" at 29.195,-96.547 h1.52
  text ".plot_File_Name" at 71.689,-96.547 h1.52
  text "PLOT NAME =" at 92.148,-96.547 h1.52
M9 Title Sheet:
  drawing of 63 lines, arcs and shapes, not listed
  text "1" at -31.207,397.25 h1.78
  text "2" at 70.266,397.25 h1.78
  text "3" at 171.739,397.25 h1.78
  text "4" at 273.365,397.25 h1.78
  text "5" at 374.923,397.25 h1.78
  text "6" at 476.48,397.25 h1.78
  text "7" at 578.123,397.25 h1.78
  text "8" at 679.596,397.25 h1.78
  text "A" at -78.374,336.341 h1.78
  text "A" at 726.806,336.341 h1.78
  text "B" at -78.374,209.341 h1.78
  text "B" at 726.806,209.341 h1.78
  text "C" at -78.374,82.341 h1.78
  text "C" at 726.806,82.341 h1.78
  text "D" at -78.374,-44.659 h1.78
  text "D" at 726.806,-44.659 h1.78
  text "PROJECT TITLE:" at 648.447,-62.677 h1.14
  text ".PRJ_Title" at 649.717,-66.064 h1.78
  text "DESIGNED FOR:" at 648.447,-70.323 h1.14
  text ".PRJ_Customer" at 649.717,-73.879 h1.78
  text "FILE NAME:" at 648.447,-77.943 h1.14
  text ".PCB_File_Name_No_Path" at 649.717,-80.991 h1.78
  text "Texas Instruments (TI) and/or its licensors do not warrant the accuracy or completeness of this specification" at 522.221,-85.101 h1.14
  text "ENGINEER:" at 648.447,-85.309 h1.14
  text "LAYOUT BY:" at 686.674,-85.309 h1.14
  text "or any information contained therein. TI and/or its licensors do not warrant that this design will meet" at 521.079,-87.963 h1.14
  text ".PRJ_Engineer" at 649.717,-89.246 h1.78
  text ".PCB_Layout" at 687.956,-89.246 h1.78
  text "the specifications, will be suitable for your application or fit for any particular purpose, or will operate in" at 521.079,-90.825 h1.14
  text ".Layer_Name" at -51.844,-91.306 h1.52
  text "ALTIUM DESIGNER VERSION:" at 686.674,-93.183 h1.14
  text "an implementation. TI and/or its licensors do not warrant that the design is production worthy. You should" at 521.079,-93.687 h1.14
  text "completely validate and test your design implementation to confirm the system functionality for your application." at 522.221,-96.548 h1.14
  text ".print_Scale" at 649.717,-96.569 h1.78
  text ".Application_BuildNumber" at 687.956,-96.569 h1.78
  text "1" at -31.207,-103.003 h1.78
  text "2" at 70.266,-103.003 h1.78
  text "3" at 171.739,-103.003 h1.78
  text "4" at 273.365,-103.003 h1.78
  text "5" at 374.923,-103.003 h1.78
  text "6" at 476.48,-103.003 h1.78
  text "7" at 578.123,-103.003 h1.78
  text "8" at 679.596,-103.003 h1.78
M10 Fab Notes:
  drawing of 189 lines, arcs and shapes, not listed
  text "DESIGN INFORMATION" at 674.876,92.175 h1.52
  text "MIN. TRACK WIDTH:" at 658.504,88.819 h1.52
  text "8" at 686.348,88.82 h1.52
  text "MIL" at 690.279,88.819 h1.52
  text "MIN. CLEARANCE:" at 658.504,85.667 h1.52
  text "7.874" at 682,85.667 h1.52
  text "MIL" at 690.279,85.667 h1.52
  text "MIN. VIA PAD SIZE:" at 658.504,82.514 h1.52
  text "24" at 685.587,82.514 h1.52
  text "MIL" at 690.279,82.514 h1.52
  text "0.05mm (2MIL)" at 676.157,79.214 h1.52
  text "MINIMUM ANNULAR RING" at 650.141,79.006 h1.52
  text "EXTERNAL" at 694.14,79.006 h1.52
  text "PER" at 655.221,76.208 h1.52
  text "IPC-D-275 CLASS 2 LEVEL C" at 660.809,76.208 h1.52
  text "MIL, HOLES" at 698.61,73.656 h1.52
  text "+/-" at 688.642,73.438 h1.52
  text "+/-" at 710.334,73.438 h1.52
  text "REGISTRATION TOLERANCES:" at 650.141,73.411 h1.52
  text "METAL" at 680.616,73.411 h1.52
  text "5" at 695.251,73.411 h1.52
  text "3" at 716.409,73.411 h1.52
  text "MIL" at 719.362,73.411 h1.52
  text "HOLE SIZE TOLERANCE (UNLESS OTHERWISE SPECIFIED):" at 650.141,70.914 h1.52
  text "+/-" at 710.334,70.841 h1.52
  text "3" at 716.409,70.814 h1.52
  text "MIL" at 719.362,70.814 h1.52
  text "MATERIAL:" at 648.242,67.318 h1.52
  text "FR-4 High Tg" at 673.298,64.053 h1.52
  text "X" at 669.629,63.85 h1.52
  text "FR-4" at 658.936,63.735 h1.52
  text "OTHER" at 696.731,63.735 h1.52
  text "62 MIL (1.6mm) +/-10%" at 667.066,60.102 h1.52
  text "X" at 664.016,60.04 h1.52
  text "THICKNESS:" at 650.141,59.894 h1.52
  text "OTHER" at 699.703,59.894 h1.52
  text "TOLERANCE:" at 650.141,56.38 h1.52
  text "X" at 671.687,56.38 h1.52
  text "ANSI IPC-6012 TYPE 3 CLASS 2" at 676.208,56.38 h1.52
  text "OTHER +/-" at 676.208,52.718 h1.52
  text "BOW & TWIST:" at 650.141,49.03 h1.52
  text "X" at 671.687,49.03 h1.52
  text "ANSI IPC-6012 TYPE 3 CLASS 2" at 676.208,49.03 h1.52
  text "OTHER +/-" at 676.208,45.304 h1.52
  text "DRILLING:" at 648.242,41.986 h1.52
  text "NC_DRILL FILES" at 692.972,39.315 h1.52
  text "REFERENCE:" at 650.141,39.215 h1.52
  text "X" at 666.835,39.212 h1.52
  text "AS SHOWN" at 671.356,39.215 h1.52
  text "X" at 689.721,39.215 h1.52
  text "OTHER" at 700.541,35.601 h1.52
  text "PTH COPPER THICKNESS:" at 650.133,35.512 h1.52
  text "X" at 679.07,35.512 h1.52
  text "20-30 um" at 682.321,35.512 h1.52
  text "BOARD FINISH:" at 648.242,31.763 h1.52
  text "SILKSCREEN:" at 652.185,28.966 h1.52
  text "X" at 676.513,28.966 h1.52
  text "TOP" at 679.484,28.966 h1.52
  text "X" at 689.467,28.966 h1.52
  text "BOTTOM" at 692.464,28.966 h1.52
  text "SILKSCREEN COLOR:" at 652.185,25.024 h1.52
  text "X" at 676.487,25.024 h1.52
  text "WHITE" at 679.484,25.024 h1.52
  text "OTHER" at 692.464,25.024 h1.52
  text "X" at 679.815,21.38 h1.52
  text "GREEN" at 682.812,21.38 h1.52
  text "OTHER" at 698.509,21.38 h1.52
  text "SOLDER RESIST COLOR:" at 652.185,21.206 h1.52
  text "X" at 679.815,17.462 h1.52
  text "MATTE" at 682.812,17.462 h1.52
  text "SEMI-GLOSS" at 698.497,17.446 h1.52
  text "IMMERSION GOLD (ENIG)" at 675.192,13.074 h1.52
  text "ENEPIG" at 709.165,12.89 h1.52
  text "SURFACE FINISH:" at 648.242,12.865 h1.52
  text "X" at 670.671,12.865 h1.52
  text "IMM. TIN/SILVER OR EQUIV" at 656.613,9.377 h1.52
  text "OTHER" at 692.972,9.277 h1.52
  text "ARRAY/PANEL:" at 648.242,5.331 h1.52
  text "CUT AND TRIM PER M1 BOARD OUTLINE" at 675.192,5.122 h1.52
  text "N.C. ROUTE" at 675.192,1.668 h1.52
  text "X" at 692.667,1.668 h1.52
  text "V. SCORE" at 697.188,1.668 h1.52
  text "CERTIFICATION:" at 648.242,-1.612 h1.52
  text "MATERIALS AND WORKMANSHIP FOR ALL PCBS" at 666.657,-1.612 h1.52
  text "TO MEET OR EXCEED THE REQUIREMENTS OF:" at 666.657,-4.001 h1.52
  text "X" at 657.45,-7.268 h1.52
  text "ANSI IPC-A-600F CLASS ->" at 660.701,-7.268 h1.52
  text "X" at 702.56,-7.268 h1.52
  text "2" at 705.354,-7.268 h1.52
  text "1" at 697.353,-7.306 h1.52
  text "3" at 714.346,-7.306 h1.52
  text "X" at 678.075,-11.019 h1.52
  text "RoHS" at 681.326,-11.019 h1.52
  text "OTHER" at 697.694,-11.019 h1.52
  text "PER ORDER" at 707.779,-11.019 h1.52
  text "ALL BOARDS MUST MEET OR EXCEED UL94-V0 REQUIREMENTS." at 648.942,-14.926 h1.52
  text "PCB MUST BEAR THE UL94V-0 UL REGISTERED MATERIAL ID NUMBER" at 648.942,-17.874 h1.52
  text "ADDITIONAL REQUIREMENTS:" at 648.242,-22.178 h1.52
  text "MICROSECTION:" at 650.141,-24.899 h1.52
  text "YES" at 673.147,-24.899 h1.52
  text "REQUIRED" at 695.029,-28.565 h1.52
  text "BARE BOARD ELEC. TEST:" at 650.141,-28.637 h1.52
  text "NONE" at 683.307,-28.637 h1.52
  text "X" at 692.032,-28.637 h1.52
  text "PER ORDER" at 710.066,-28.637 h1.52
  text "XX MIL VIAS REQUIRE NON-CONDUCTIVE FILL AND PLANARIZE" at 654.412,-33.843 h1.5
  text "XX MIL VIAS REQUIRE CONDUCTIVE FILL AND PLANARIZE" at 654.616,-36.484 h1.52
  text "OUTER XX MIL TRACES REQUIRE 50 OHM SINGLE-ENDED IMPEDANCE" at 654.591,-40.634 h1.47
  text "LAYER 2 & 3 (INNER LAYERS) XX MIL WIDE, XX MIL SPACE / TRACES REQUIRE 100 OHM DIFFERENTIAL IMPEDANCE" at 654.387,-46.621 h1.52
  text ".Layer_Name" at -51.844,-91.306 h1.52
M11 Gerber Information:
  lines w0.254: -73.917,-93.126 93.723,-93.126 ; -73.917,-87.962 93.774,-87.962 ; -73.917,-82.797 -73.917,-98.291 27.81,-98.291 93.774,-98.291 93.774,-82.797 -73.904,-82.797 -73.904,-98.291 -33.886,-98.291 ; -11.306,-98.291 -11.306,-82.797 ; 20.876,-87.962 20.876,-82.797 ; 42.212,-87.962 42.212,-82.797 ; 58.011,-98.456 58.011,-93.304
  text "ALL ARTWORK VIEWED FROM TOP SIDE" at -72.304,-86.154 h1.52
  text "BOARD #:" at -9.401,-86.154 h1.52
  text ".PRJ_Number" at 4.455,-86.154 h1.52
  text "REV:" at 25.905,-86.154 h1.52
  text ".PCB_Rev" at 33.309,-86.154 h1.52
  text "SVN REV:" at 47.19,-86.154 h1.52
  text ".VersionControl_RevNumber" at 60.043,-86.154 h1.52
  text "LAYER NAME =" at -72.304,-91.306 h1.52
  text "PLOT NAME =" at -72.304,-96.534 h1.52
  text ".plot_File_Name" at -51.844,-96.534 h1.52
  text "GENERATED    :" at -9.35,-96.534 h1.52
  text ".Print_Date" at 12.735,-96.534 h1.52
  text ".Print_Time" at 31.252,-96.534 h1.52
  text "TEXAS INSTRUMENTS" at 63.37,-96.534 h1.52
M12 Stackup:
  drawing of 295 lines, arcs and shapes, not listed
  text "Layer" at 607.969,388.024 h1.52
  text "Name" at 618.38,388.024 h1.52
  text "Material" at 641.996,388.024 h1.52
  text "Thickness" at 663.834,388.024 h1.52
  text "Constant" at 680.34,388.024 h1.52
  text "Board Layer Stack" at 694.814,388.024 h1.52
  text "Top Overlay" at 618.38,384.976 h1.52
  text "Top Solder" at 618.38,381.928 h1.52
  text "Solder Resist" at 641.996,381.928 h1.52
  text "0.40mil" at 663.834,381.928 h1.52
  text "3.5" at 680.34,381.928 h1.52
  text "1" at 607.969,378.88 h1.52
  text "Top Layer" at 618.38,378.88 h1.52
  text "2.76mil" at 663.834,378.88 h1.52
  text "Dielectric 1" at 618.38,375.832 h1.52
  text "FR-4 High Tg" at 641.996,375.832 h1.52
  text "8.00mil" at 663.834,375.832 h1.52
  text "4.2" at 680.34,375.832 h1.52
  text "2" at 607.969,372.784 h1.52
  text "Signal Layer1" at 618.38,372.784 h1.52
  text "CF-004" at 641.996,372.784 h1.52
  text "2.76mil" at 663.834,372.784 h1.52
  text "Dielectric1" at 618.38,369.736 h1.52
  text "FR-4 High Tg" at 641.996,369.736 h1.52
  text "37.20mil" at 663.834,369.736 h1.52
  text "4.2" at 680.34,369.736 h1.52
  text "3" at 607.969,366.688 h1.52
  text "Signal Layer2" at 618.38,366.688 h1.52
  text "CF-004" at 641.996,366.688 h1.52
  text "2.76mil" at 663.834,366.688 h1.52
  text "Dielectric 2" at 618.38,363.64 h1.52
  text "FR-4 High Tg" at 641.996,363.64 h1.52
  text "8.00mil" at 663.834,363.64 h1.52
  text "4.2" at 680.34,363.64 h1.52
  text "4" at 607.969,360.592 h1.52
  text "Bottom Layer" at 618.38,360.592 h1.52
  text "2.76mil" at 663.834,360.592 h1.52
  text "Bottom Solder" at 618.38,357.544 h1.52
  text "Solder Resist" at 641.996,357.544 h1.52
  text "0.40mil" at 663.834,357.544 h1.52
  text "3.5" at 680.34,357.544 h1.52
  text "Bottom Overlay" at 618.38,354.496 h1.52
  text ".Layer_Name" at -51.844,-91.306 h1.52
M13 Component Bodies Top:
  text ".Layer_Name" at -51.844,-91.306 h1.52
M14 Component Bodies Bottom:
  text ".Layer_Name" at -51.844,-91.306 h1.52
M15 Courtyards Top:
  text ".Layer_Name" at -51.844,-91.306 h1.52
M16 Courtyards Bottom:
  text ".Layer_Name" at -51.844,-91.306 h1.52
